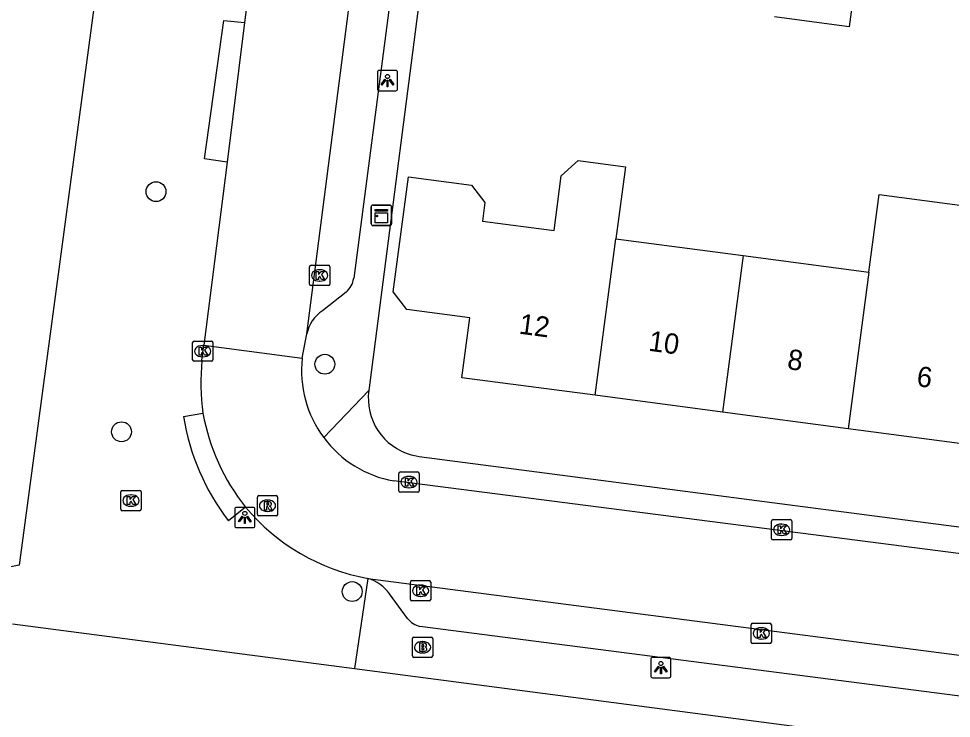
# Model space of a CAD drawing. Extents: x 162186 to 163152, y 385513 to 386513.
# Drawn here: x 162356.56 to 162402.52, y 386190.69 to 386225.15 of the extents above; entities that cross this region are included whole.
import ezdxf

# ---------------------------------------------------------------- set-up
doc = ezdxf.new("R2010")
doc.units = 0
for name, color, linetype in [('IMGEO_Boom', 7, 'Continuous'), ('IMGEO_Brandkraan', 7, 'Continuous'), ('IMGEO_Kast', 7, 'Continuous'), ('IMGEO_Kolk', 7, 'Continuous'), ('IMGEO_Lichtpunt', 7, 'Continuous'), ('IMGEO_Pand', 7, 'Continuous'), ('IMGEO_Pand_nummerreeks', 7, 'Continuous'), ('IMGEO_Rijbaan_lokaal_open', 7, 'Continuous'), ('IMGEO_Rioolput', 7, 'Continuous'), ('IMGEO_Voetpad_open', 7, 'Continuous')]:
    doc.layers.add(name, color=color, linetype=linetype)

msp = doc.modelspace()

# ---------------------------------------------------------------- linework, layer by layer
at = {"layer": 'IMGEO_Boom'}
for centre in [(162363.329, 386216.63), (162371.647, 386208.129), (162361.626, 386204.803), (162372.997, 386196.933)]:
    msp.add_circle(centre, 0.489, dxfattribs=at)
at = {"layer": 'IMGEO_Brandkraan'}
for p, q in [((162375.962, 386193.764), (162375.962, 386194.616)), ((162376.037, 386194.69), (162376.889, 386194.69)), ((162376.45, 386194.47), (162376.475, 386194.47)), ((162376.963, 386194.616), (162376.963, 386193.764)), ((162376.473, 386193.91), (162376.448, 386193.91)), ((162376.889, 386193.69), (162376.037, 386193.69))]:
    msp.add_line(p, q, dxfattribs=at)
for points in [[(162375.962, 386193.764), (162375.962, 386194.616)], [(162376.037, 386194.69), (162376.889, 386194.69)], [(162376.31, 386194.39), (162376.31, 386193.99), (162376.523, 386193.99)], [(162376.541, 386194.39), (162376.31, 386194.39)], [(162376.489, 386194.309), (162376.435, 386194.309), (162376.435, 386194.233)], [(162376.963, 386194.616), (162376.963, 386193.764)], [(162376.435, 386194.233), (162376.488, 386194.233)], [(162376.497, 386194.157), (162376.435, 386194.157), (162376.435, 386194.076)], [(162376.435, 386194.076), (162376.497, 386194.076)], [(162376.889, 386193.69), (162376.037, 386193.69)]]:
    msp.add_lwpolyline(points, dxfattribs=at)
for centre, radius, start, end in [((162376.039, 386194.614), 0.0765, 91.552, 178.448), ((162376.039, 386194.614), 0.0765, 91.552, 178.448), ((162376.49, 386194.271), 0.0379, 267.8285, 90.9355), ((162376.545, 386194.245), 0.145, 59.4692, 91.5367), ((162376.57, 386194.292), 0.0922, 285.5137, 58.1501), ((162376.887, 386194.614), 0.0765, 1.552, 88.448), ((162376.887, 386194.614), 0.0765, 1.552, 88.448), ((162376.498, 386194.116), 0.0404, 269.8759, 90.5077), ((162376.529, 386194.241), 0.251, 268.6676, 293.5347), ((162376.575, 386194.1), 0.105, 301.3115, 78.989), ((162376.039, 386193.766), 0.0765, 181.552, 268.448), ((162376.039, 386193.766), 0.0765, 181.552, 268.448), ((162376.887, 386193.766), 0.0765, 271.552, 358.448), ((162376.887, 386193.766), 0.0765, 271.552, 358.448)]:
    msp.add_arc(centre, radius, start, end, dxfattribs=at)
for centre, major_axis, ratio, start_param, end_param in [((162376.449, 386194.19), (-0.387, 0.002), 0.722429, 4.712389, 7.853982), ((162376.474, 386194.19), (-0.39, 0.002), 0.717154, 1.570796, 4.712389)]:
    msp.add_ellipse(centre, major_axis=major_axis, ratio=ratio, start_param=start_param, end_param=end_param, dxfattribs=at)
at = {"layer": 'IMGEO_Kast'}
for p, q in [((162373.935, 386215.04), (162373.935, 386215.881)), ((162373.935, 386215.881), (162373.935, 386215.04)), ((162374.01, 386215.965), (162374.851, 386215.965)), ((162374.851, 386215.965), (162374.01, 386215.965)), ((162374.935, 386215.89), (162374.935, 386215.049)), ((162374.935, 386215.049), (162374.935, 386215.89)), ((162374.86, 386214.965), (162374.019, 386214.965)), ((162374.019, 386214.965), (162374.86, 386214.965))]:
    msp.add_line(p, q, dxfattribs=at)
for points in [[(162374.13, 386215.755), (162374.73, 386215.755), (162374.73, 386215.67), (162374.13, 386215.67), (162374.13, 386215.755)], [(162374.13, 386215.58), (162374.73, 386215.58), (162374.73, 386215.091), (162374.13, 386215.091), (162374.13, 386215.58)]]:
    msp.add_lwpolyline(points, dxfattribs=at)
msp.add_circle((162374.214, 386215.429), 0.0377, dxfattribs=at)
for centre, start, end in [((162374.013, 386215.887), 92.4484, 184.2845), ((162374.013, 386215.887), 92.4484, 184.2845), ((162374.857, 386215.887), 2.4484, 94.2845), ((162374.857, 386215.887), 2.4484, 94.2845), ((162374.013, 386215.043), 182.4484, 274.2845), ((162374.013, 386215.043), 182.4484, 274.2845), ((162374.857, 386215.043), 272.4484, 4.2845), ((162374.857, 386215.043), 272.4484, 4.2845)]:
    msp.add_arc(centre, 0.0779, start, end, dxfattribs=at)
at = {"layer": 'IMGEO_Kolk'}
for p, q in [((162370.894, 386212.077), (162370.894, 386212.929)), ((162370.969, 386213.003), (162371.821, 386213.003)), ((162371.382, 386212.783), (162371.407, 386212.783)), ((162371.895, 386212.929), (162371.895, 386212.077)), ((162371.405, 386212.223), (162371.38, 386212.223)), ((162371.821, 386212.003), (162370.969, 386212.003)), ((162365.131, 386208.348), (162365.131, 386209.2)), ((162365.206, 386209.274), (162366.058, 386209.274)), ((162365.619, 386209.054), (162365.644, 386209.054)), ((162366.132, 386209.2), (162366.132, 386208.348)), ((162366.058, 386208.274), (162365.206, 386208.274)), ((162365.642, 386208.494), (162365.617, 386208.494)), ((162375.295, 386201.897), (162375.295, 386202.749)), ((162375.37, 386202.823), (162376.222, 386202.823)), ((162375.783, 386202.603), (162375.808, 386202.603)), ((162376.296, 386202.749), (162376.296, 386201.897)), ((162361.593, 386200.991), (162361.593, 386201.843)), ((162361.668, 386201.917), (162362.52, 386201.917)), ((162362.081, 386201.697), (162362.106, 386201.697)), ((162362.594, 386201.843), (162362.594, 386200.991)), ((162376.222, 386201.823), (162375.37, 386201.823)), ((162375.806, 386202.043), (162375.781, 386202.043)), ((162362.52, 386200.917), (162361.668, 386200.917)), ((162362.104, 386201.137), (162362.079, 386201.137)), ((162393.662, 386199.549), (162393.662, 386200.401)), ((162393.737, 386200.475), (162394.589, 386200.475)), ((162394.15, 386200.255), (162394.175, 386200.255)), ((162394.663, 386200.401), (162394.663, 386199.549)), ((162394.589, 386199.475), (162393.737, 386199.475)), ((162394.173, 386199.695), (162394.148, 386199.695)), ((162375.94, 386197.474), (162376.792, 386197.474)), ((162375.865, 386196.548), (162375.865, 386197.4)), ((162376.353, 386197.254), (162376.378, 386197.254)), ((162376.866, 386197.4), (162376.866, 386196.548)), ((162376.376, 386196.694), (162376.351, 386196.694)), ((162376.792, 386196.474), (162375.94, 386196.474)), ((162392.657, 386194.445), (162392.657, 386195.297)), ((162392.732, 386195.371), (162393.584, 386195.371)), ((162393.658, 386195.297), (162393.658, 386194.445)), ((162393.145, 386195.151), (162393.17, 386195.151)), ((162393.584, 386194.371), (162392.732, 386194.371)), ((162393.168, 386194.591), (162393.143, 386194.591))]:
    msp.add_line(p, q, dxfattribs=at)
for points in [[(162370.894, 386212.077), (162370.894, 386212.929)], [(162370.969, 386213.003), (162371.821, 386213.003)], [(162371.215, 386212.703), (162371.338, 386212.703), (162371.338, 386212.552), (162371.468, 386212.703), (162371.632, 386212.703), (162371.486, 386212.552), (162371.639, 386212.303), (162371.487, 386212.303), (162371.402, 386212.467), (162371.338, 386212.4), (162371.338, 386212.303), (162371.215, 386212.303), (162371.215, 386212.703)], [(162371.895, 386212.929), (162371.895, 386212.077)], [(162371.821, 386212.003), (162370.969, 386212.003)], [(162365.131, 386208.348), (162365.131, 386209.2)], [(162365.206, 386209.274), (162366.058, 386209.274)], [(162365.452, 386208.974), (162365.575, 386208.974), (162365.575, 386208.823), (162365.705, 386208.974), (162365.869, 386208.974), (162365.723, 386208.823), (162365.876, 386208.574), (162365.724, 386208.574), (162365.639, 386208.738), (162365.575, 386208.671), (162365.575, 386208.574), (162365.452, 386208.574), (162365.452, 386208.974)], [(162366.132, 386209.2), (162366.132, 386208.348)], [(162366.058, 386208.274), (162365.206, 386208.274)], [(162375.295, 386201.897), (162375.295, 386202.749)], [(162375.37, 386202.823), (162376.222, 386202.823)], [(162375.616, 386202.523), (162375.739, 386202.523), (162375.739, 386202.372), (162375.869, 386202.523), (162376.033, 386202.523), (162375.887, 386202.372), (162376.04, 386202.123), (162375.888, 386202.123), (162375.803, 386202.287), (162375.739, 386202.22), (162375.739, 386202.123), (162375.616, 386202.123), (162375.616, 386202.523)], [(162376.296, 386202.749), (162376.296, 386201.897)], [(162361.593, 386200.991), (162361.593, 386201.843)], [(162361.668, 386201.917), (162362.52, 386201.917)], [(162361.914, 386201.617), (162362.037, 386201.617), (162362.037, 386201.466), (162362.167, 386201.617), (162362.331, 386201.617), (162362.185, 386201.466), (162362.338, 386201.217), (162362.186, 386201.217), (162362.101, 386201.381), (162362.037, 386201.314), (162362.037, 386201.217), (162361.914, 386201.217), (162361.914, 386201.617)], [(162362.594, 386201.843), (162362.594, 386200.991)], [(162376.222, 386201.823), (162375.37, 386201.823)], [(162362.52, 386200.917), (162361.668, 386200.917)], [(162393.662, 386199.549), (162393.662, 386200.401)], [(162393.737, 386200.475), (162394.589, 386200.475)], [(162394.663, 386200.401), (162394.663, 386199.549)], [(162393.983, 386200.175), (162394.106, 386200.175), (162394.106, 386200.024), (162394.236, 386200.175), (162394.4, 386200.175), (162394.254, 386200.024), (162394.407, 386199.775), (162394.255, 386199.775), (162394.17, 386199.939), (162394.106, 386199.872), (162394.106, 386199.775), (162393.983, 386199.775), (162393.983, 386200.175)], [(162394.589, 386199.475), (162393.737, 386199.475)], [(162375.94, 386197.474), (162376.792, 386197.474)], [(162375.865, 386196.548), (162375.865, 386197.4)], [(162376.186, 386197.174), (162376.309, 386197.174), (162376.309, 386197.023), (162376.439, 386197.174), (162376.603, 386197.174), (162376.457, 386197.023), (162376.61, 386196.774), (162376.458, 386196.774), (162376.373, 386196.938), (162376.309, 386196.871), (162376.309, 386196.774), (162376.186, 386196.774), (162376.186, 386197.174)], [(162376.866, 386197.4), (162376.866, 386196.548)], [(162376.792, 386196.474), (162375.94, 386196.474)], [(162392.657, 386194.445), (162392.657, 386195.297)], [(162392.732, 386195.371), (162393.584, 386195.371)], [(162393.658, 386195.297), (162393.658, 386194.445)], [(162392.978, 386195.071), (162393.101, 386195.071), (162393.101, 386194.92), (162393.231, 386195.071), (162393.395, 386195.071), (162393.249, 386194.92), (162393.402, 386194.671), (162393.25, 386194.671), (162393.165, 386194.835), (162393.101, 386194.768), (162393.101, 386194.671), (162392.978, 386194.671), (162392.978, 386195.071)], [(162393.584, 386194.371), (162392.732, 386194.371)]]:
    msp.add_lwpolyline(points, dxfattribs=at)
for centre, start, end in [((162370.971, 386212.927), 91.552, 178.448), ((162370.971, 386212.927), 91.552, 178.448), ((162371.819, 386212.927), 1.552, 88.448), ((162371.819, 386212.927), 1.552, 88.448), ((162370.971, 386212.079), 181.552, 268.448), ((162370.971, 386212.079), 181.552, 268.448), ((162371.819, 386212.079), 271.552, 358.448), ((162371.819, 386212.079), 271.552, 358.448), ((162365.208, 386209.198), 91.552, 178.448), ((162365.208, 386209.198), 91.552, 178.448), ((162366.056, 386209.198), 1.552, 88.448), ((162366.056, 386209.198), 1.552, 88.448), ((162365.208, 386208.35), 181.552, 268.448), ((162365.208, 386208.35), 181.552, 268.448), ((162366.056, 386208.35), 271.552, 358.448), ((162366.056, 386208.35), 271.552, 358.448), ((162375.372, 386202.747), 91.552, 178.448), ((162375.372, 386202.747), 91.552, 178.448), ((162376.22, 386202.747), 1.552, 88.448), ((162376.22, 386202.747), 1.552, 88.448), ((162361.67, 386201.841), 91.552, 178.448), ((162361.67, 386201.841), 91.552, 178.448), ((162362.518, 386201.841), 1.552, 88.448), ((162362.518, 386201.841), 1.552, 88.448), ((162375.372, 386201.899), 181.552, 268.448), ((162375.372, 386201.899), 181.552, 268.448), ((162376.22, 386201.899), 271.552, 358.448), ((162376.22, 386201.899), 271.552, 358.448), ((162361.67, 386200.993), 181.552, 268.448), ((162361.67, 386200.993), 181.552, 268.448), ((162362.518, 386200.993), 271.552, 358.448), ((162362.518, 386200.993), 271.552, 358.448), ((162393.739, 386200.399), 91.552, 178.448), ((162393.739, 386200.399), 91.552, 178.448), ((162394.587, 386200.399), 1.552, 88.448), ((162394.587, 386200.399), 1.552, 88.448), ((162393.739, 386199.551), 181.552, 268.448), ((162393.739, 386199.551), 181.552, 268.448), ((162394.587, 386199.551), 271.552, 358.448), ((162394.587, 386199.551), 271.552, 358.448), ((162375.942, 386197.398), 91.552, 178.448), ((162375.942, 386197.398), 91.552, 178.448), ((162376.79, 386197.398), 1.552, 88.448), ((162376.79, 386197.398), 1.552, 88.448), ((162375.942, 386196.55), 181.552, 268.448), ((162375.942, 386196.55), 181.552, 268.448), ((162376.79, 386196.55), 271.552, 358.448), ((162376.79, 386196.55), 271.552, 358.448), ((162392.734, 386195.295), 91.552, 178.448), ((162392.734, 386195.295), 91.552, 178.448), ((162393.582, 386195.295), 1.552, 88.448), ((162393.582, 386195.295), 1.552, 88.448), ((162392.734, 386194.447), 181.552, 268.448), ((162392.734, 386194.447), 181.552, 268.448), ((162393.582, 386194.447), 271.552, 358.448), ((162393.582, 386194.447), 271.552, 358.448)]:
    msp.add_arc(centre, 0.0765, start, end, dxfattribs=at)
for centre, major_axis, ratio, start_param, end_param in [((162371.381, 386212.503), (-0.387, 0.002), 0.722429, 4.712389, 7.853982), ((162371.406, 386212.503), (-0.39, 0.002), 0.717154, 1.570796, 4.712389), ((162365.618, 386208.774), (-0.387, 0.002), 0.722429, 4.712389, 7.853982), ((162365.643, 386208.774), (-0.39, 0.002), 0.717154, 1.570796, 4.712389), ((162375.782, 386202.323), (-0.387, 0.002), 0.722429, 4.712389, 7.853982), ((162375.807, 386202.323), (-0.39, 0.002), 0.717154, 1.570796, 4.712389), ((162362.08, 386201.417), (-0.387, 0.002), 0.722429, 4.712389, 7.853982), ((162362.105, 386201.417), (-0.39, 0.002), 0.717154, 1.570796, 4.712389), ((162394.149, 386199.975), (-0.387, 0.002), 0.722429, 4.712389, 7.853982), ((162394.174, 386199.975), (-0.39, 0.002), 0.717154, 1.570796, 4.712389), ((162376.352, 386196.974), (-0.387, 0.002), 0.722429, 4.712389, 7.853982), ((162376.377, 386196.974), (-0.39, 0.002), 0.717154, 1.570796, 4.712389), ((162393.144, 386194.871), (-0.387, 0.002), 0.722429, 4.712389, 7.853982), ((162393.169, 386194.871), (-0.39, 0.002), 0.717154, 1.570796, 4.712389)]:
    msp.add_ellipse(centre, major_axis=major_axis, ratio=ratio, start_param=start_param, end_param=end_param, dxfattribs=at)
at = {"layer": 'IMGEO_Lichtpunt'}
for p, q in [((162374.238, 386222.504), (162374.238, 386221.697)), ((162374.238, 386222.504), (162374.238, 386221.697)), ((162375.14, 386222.599), (162374.332, 386222.599)), ((162375.14, 386222.599), (162374.332, 386222.599)), ((162375.234, 386221.697), (162375.234, 386222.504)), ((162375.234, 386221.697), (162375.234, 386222.504)), ((162374.332, 386221.603), (162375.14, 386221.603)), ((162374.332, 386221.603), (162375.14, 386221.603)), ((162367.206, 386200.986), (162367.206, 386200.179)), ((162367.206, 386200.986), (162367.206, 386200.179)), ((162368.108, 386201.081), (162367.3, 386201.081)), ((162368.108, 386201.081), (162367.3, 386201.081)), ((162368.202, 386200.179), (162368.202, 386200.986)), ((162368.202, 386200.179), (162368.202, 386200.986)), ((162367.3, 386200.085), (162368.108, 386200.085)), ((162367.3, 386200.085), (162368.108, 386200.085)), ((162387.71, 386193.591), (162387.71, 386192.784)), ((162387.71, 386193.591), (162387.71, 386192.784)), ((162388.612, 386193.686), (162387.804, 386193.686)), ((162388.612, 386193.686), (162387.804, 386193.686)), ((162388.706, 386192.784), (162388.706, 386193.591)), ((162388.706, 386192.784), (162388.706, 386193.591)), ((162387.804, 386192.69), (162388.612, 386192.69)), ((162387.804, 386192.69), (162388.612, 386192.69))]:
    msp.add_line(p, q, dxfattribs=at)
for points in [[(162374.612, 386222.168), (162374.651, 386222.14), (162374.463, 386221.878), (162374.425, 386221.905), (162374.612, 386222.168)], [(162374.714, 386222.12), (162374.761, 386222.12), (162374.761, 386221.798), (162374.714, 386221.798), (162374.714, 386222.12)], [(162374.824, 386222.14), (162374.862, 386222.167), (162375.049, 386221.905), (162375.01, 386221.877), (162374.824, 386222.14)], [(162367.58, 386200.65), (162367.619, 386200.622), (162367.431, 386200.36), (162367.393, 386200.387), (162367.58, 386200.65)], [(162367.682, 386200.602), (162367.729, 386200.602), (162367.729, 386200.28), (162367.682, 386200.28), (162367.682, 386200.602)], [(162367.792, 386200.622), (162367.83, 386200.649), (162368.017, 386200.387), (162367.978, 386200.359), (162367.792, 386200.622)], [(162388.084, 386193.255), (162388.123, 386193.227), (162387.935, 386192.965), (162387.897, 386192.992), (162388.084, 386193.255)], [(162388.186, 386193.207), (162388.233, 386193.207), (162388.233, 386192.885), (162388.186, 386192.885), (162388.186, 386193.207)], [(162388.296, 386193.227), (162388.334, 386193.254), (162388.521, 386192.992), (162388.482, 386192.964), (162388.296, 386193.227)]]:
    msp.add_lwpolyline(points, dxfattribs=at)
for centre in [(162374.737, 386222.302), (162367.705, 386200.784), (162388.209, 386193.389)]:
    msp.add_circle(centre, 0.0994, dxfattribs=at)
for centre, start, end in [((162374.332, 386222.504), 90, 180), ((162374.332, 386222.504), 90, 180), ((162375.14, 386222.504), 0, 90), ((162375.14, 386222.504), 0, 90), ((162374.332, 386221.697), 180, 270), ((162374.332, 386221.697), 180, 270), ((162375.14, 386221.697), 270, 0), ((162375.14, 386221.697), 270, 360), ((162367.3, 386200.986), 90, 180), ((162367.3, 386200.986), 90, 180), ((162368.108, 386200.986), 0, 90), ((162368.108, 386200.986), 0, 90), ((162367.3, 386200.179), 180, 270), ((162367.3, 386200.179), 180, 270), ((162368.108, 386200.179), 270, 0), ((162368.108, 386200.179), 270, 360), ((162387.804, 386193.591), 90, 180), ((162387.804, 386193.591), 90, 180), ((162388.612, 386193.591), 0, 90), ((162388.612, 386193.591), 0, 90), ((162387.804, 386192.784), 180, 270), ((162387.804, 386192.784), 180, 270), ((162388.612, 386192.784), 270, 0), ((162388.612, 386192.784), 270, 360)]:
    msp.add_arc(centre, 0.0946, start, end, dxfattribs=at)
at = {"layer": 'IMGEO_Pand'}
for points in [[(162397.81, 386227.229), (162397.483, 386224.754), (162393.815, 386225.238)], [(162384.979, 386206.599), (162378.396, 386207.467), (162378.786, 386210.422), (162375.683, 386210.832), (162375.021, 386211.697), (162375.771, 386217.368), (162378.872, 386216.958), (162379.535, 386216.094), (162379.413, 386215.177), (162382.948, 386214.711), (162383.303, 386217.407), (162384.135, 386218.165), (162386.461, 386217.859), (162385.994, 386214.309)], [(162398.463, 386212.664), (162398.969, 386216.489), (162405.416, 386215.636), (162404.942, 386211.81)], [(162384.979, 386206.599), (162385.994, 386214.309)], [(162385.994, 386214.309), (162392.259, 386213.483)], [(162392.259, 386213.483), (162391.239, 386205.773)], [(162392.259, 386213.483), (162398.463, 386212.664)], [(162398.463, 386212.664), (162397.443, 386204.955)], [(162391.239, 386205.773), (162384.979, 386206.599)], [(162397.443, 386204.955), (162391.239, 386205.773)], [(162403.922, 386204.1), (162397.443, 386204.955)]]:
    msp.add_lwpolyline(points, dxfattribs=at)
at = {"layer": 'IMGEO_Rijbaan_lokaal_open'}
for points in [[(162370.766, 386209.623), (162376.791, 386256.355)], [(162371.12, 386251.415), (162367.693, 386224.969)], [(162367.693, 386224.969), (162366.839, 386218.083)], [(162366.839, 386218.083), (162365.688, 386209.063)], [(162370.536, 386208.433), (162370.766, 386209.623)], [(162365.594, 386208.324), (162365.688, 386209.063)], [(162365.688, 386209.063), (162370.536, 386208.433)], [(162416.792, 386197.026), (162375.043, 386202.382)], [(162373.772, 386197.58), (162439.563, 386189.058)]]:
    msp.add_lwpolyline(points, dxfattribs=at)
for centre, radius, start, end in [((162377.089, 386207.23), 11.547, 174.5632, 187.544), ((162376.017, 386207.813), 5.516, 173.5444, 216.6933), ((162375.971, 386207.606), 10.501, 190.3821, 218.3432), ((162376.018, 386207.811), 5.516, 216.6672, 259.8161), ((162375.618, 386207.698), 10.285, 219.9623, 259.6606)]:
    msp.add_arc(centre, radius, start, end, dxfattribs=at)
at = {"layer": 'IMGEO_Rioolput'}
for p, q in [((162368.397, 386201.661), (162369.249, 386201.661)), ((162368.322, 386200.735), (162368.322, 386201.587)), ((162368.81, 386201.441), (162368.835, 386201.441)), ((162369.323, 386201.587), (162369.323, 386200.735)), ((162368.833, 386200.881), (162368.808, 386200.881)), ((162369.249, 386200.661), (162368.397, 386200.661))]:
    msp.add_line(p, q, dxfattribs=at)
for points in [[(162368.397, 386201.661), (162369.249, 386201.661)], [(162368.322, 386200.735), (162368.322, 386201.587)], [(162368.911, 386201.359), (162368.659, 386201.361), (162368.659, 386200.961)], [(162368.837, 386201.28), (162368.783, 386201.28), (162368.783, 386201.199)], [(162368.783, 386201.199), (162368.835, 386201.199)], [(162369.323, 386201.587), (162369.323, 386200.735)], [(162368.659, 386200.961), (162368.783, 386200.961), (162368.783, 386201.123), (162368.794, 386201.123)], [(162368.841, 386201.094), (162368.912, 386200.961), (162369.052, 386200.961), (162368.987, 386201.087)], [(162369.249, 386200.661), (162368.397, 386200.661)]]:
    msp.add_lwpolyline(points, dxfattribs=at)
for centre, radius, start, end in [((162368.399, 386201.585), 0.0765, 91.552, 178.448), ((162368.399, 386201.585), 0.0765, 91.552, 178.448), ((162369.247, 386201.585), 0.0765, 1.552, 88.448), ((162369.247, 386201.585), 0.0765, 1.552, 88.448), ((162368.819, 386201.388), 0.19, 274.7715, 282.9687), ((162368.843, 386201.184), 0.0964, 77.0061, 93.1865), ((162368.857, 386201.241), 0.0378, 276.6634, 79.6772), ((162368.91, 386201.249), 0.109, 350.3612, 89.416), ((162368.908, 386201.249), 0.112, 277.5842, 350.9817), ((162368.399, 386200.737), 0.0765, 181.552, 268.448), ((162368.399, 386200.737), 0.0765, 181.552, 268.448), ((162368.793, 386201.07), 0.0533, 26.0293, 88.6989), ((162368.892, 386201.034), 0.108, 29.5134, 73.7905), ((162369.247, 386200.737), 0.0765, 271.552, 358.448), ((162369.247, 386200.737), 0.0765, 271.552, 358.448)]:
    msp.add_arc(centre, radius, start, end, dxfattribs=at)
for centre, major_axis, ratio, start_param, end_param in [((162368.809, 386201.161), (-0.387, 0.002), 0.722429, 4.712389, 7.853982), ((162368.834, 386201.161), (-0.39, 0.002), 0.717154, 1.570796, 4.712389)]:
    msp.add_ellipse(centre, major_axis=major_axis, ratio=ratio, start_param=start_param, end_param=end_param, dxfattribs=at)
at = {"layer": 'IMGEO_Voetpad_open'}
for points in [[(162376.857, 386230.36), (162373.813, 386206.829)], [(162364.937, 386227.707), (162360.618, 386228.401), (162356.582, 386198.235), (162355.492, 386198.013)], [(162374.902, 386226.342), (162373.069, 386212.366)], [(162366.839, 386218.083), (162365.724, 386218.245), (162366.678, 386225.064), (162367.693, 386224.969)], [(162372.694, 386211.684), (162371.525, 386210.758)], [(162373.813, 386206.829), (162371.594, 386204.517)], [(162373.813, 386206.829), (162373.791, 386206.572), (162373.792, 386206.314), (162373.816, 386206.057), (162373.862, 386205.804), (162373.932, 386205.555), (162374.023, 386205.314), (162374.135, 386205.082), (162374.268, 386204.861), (162374.419, 386204.652), (162374.589, 386204.458), (162374.776, 386204.28), (162374.977, 386204.12), (162375.192, 386203.978), (162375.419, 386203.855), (162375.657, 386203.754), (162375.902, 386203.674), (162376.153, 386203.616), (162376.301, 386203.593), (162416.137, 386198.403)], [(162364.68, 386205.555), (162365.642, 386205.714)], [(162367.735, 386201.092), (162366.894, 386200.414)], [(162373.772, 386197.58), (162373.114, 386193.137)], [(162375.721, 386195.603), (162374.84, 386196.819)], [(162356.255, 386195.346), (162373.114, 386193.137)], [(162413.653, 386190.403), (162376.336, 386195.211)], [(162373.114, 386193.137), (162483.993, 386178.608)]]:
    msp.add_lwpolyline(points, dxfattribs=at)
for centre, radius, start, end in [((162371.98, 386212.521), 1.1, 310.4736, 351.9177), ((162372.436, 386209.328), 1.695, 122.4829, 169.974), ((162376.119, 386207.434), 11.593, 189.329, 217.2698), ((162373.189, 386195.632), 2.033, 35.7141, 73.3426), ((162376.642, 386196.369), 1.198, 219.758, 255.2152)]:
    msp.add_arc(centre, radius, start, end, dxfattribs=at)

# ---------------------------------------------------------------- texts
at = {"layer": 'IMGEO_Pand_nummerreeks'}
for s, rotation, p in [('12', 352.486, (162381.182, 386209.641)), ('10', 352.486, (162387.567, 386208.799)), ('8', 352.486, (162394.402, 386207.897)), ('6', 352.4885, (162400.777, 386207.057))]:
    msp.add_text(s, height=1, rotation=rotation, dxfattribs=at).set_placement(p)

doc.saveas('drawing.dxf')
